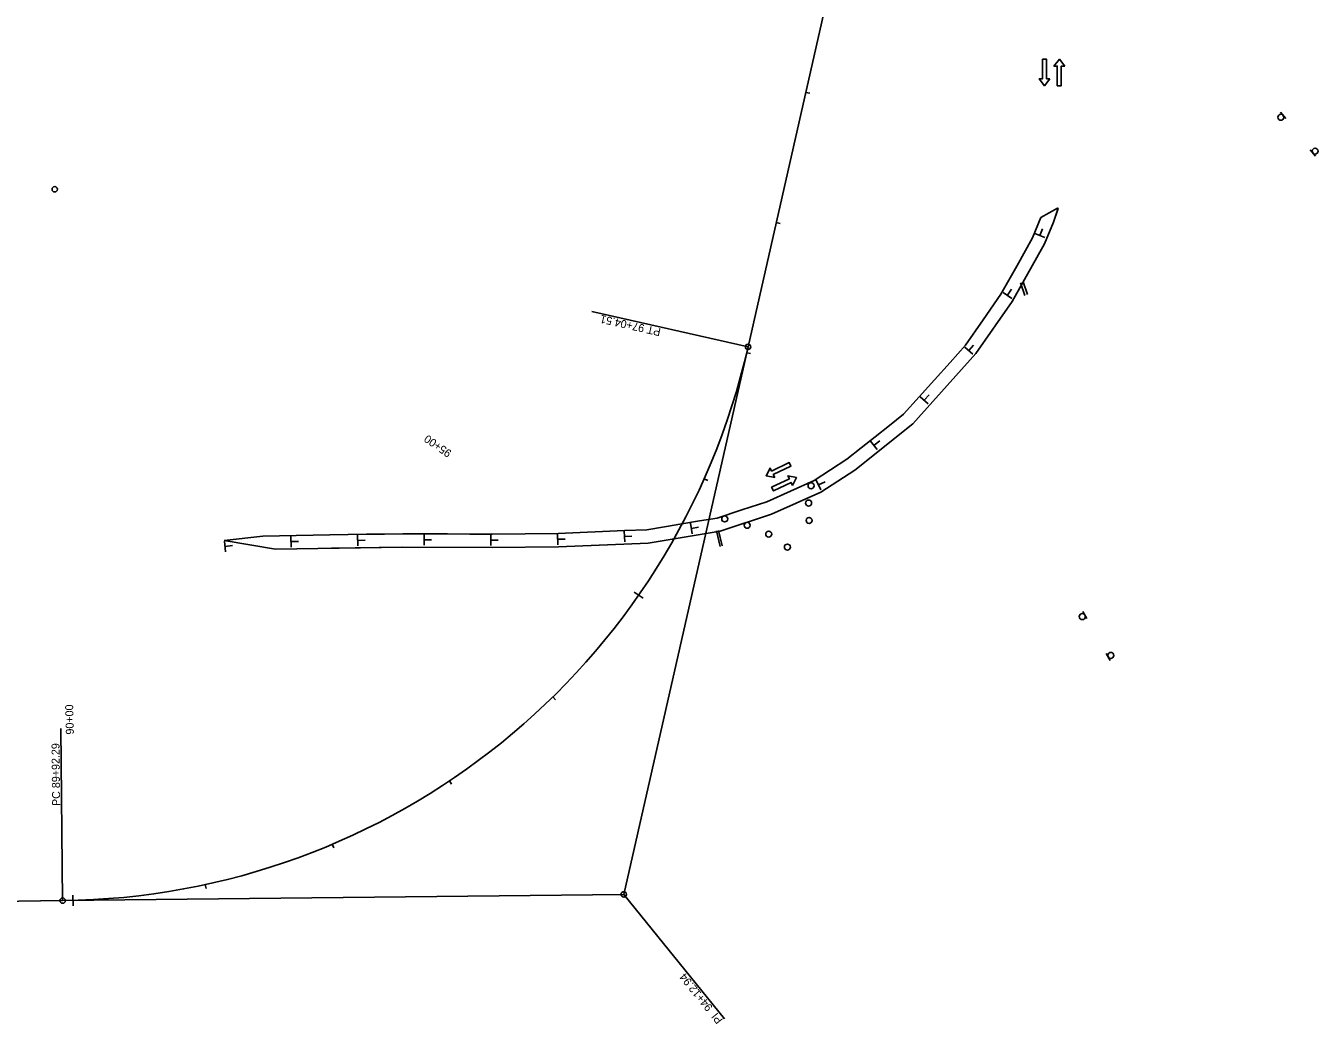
# Model space of a CAD drawing. Extents: x 1710760 to 1712674, y 548603 to 551099.
# Drawn here: x 1711705 to 1712674, y 549120 to 549868 of the extents above; entities that cross this region are included whole.
import ezdxf

# ---------------------------------------------------------------- set-up
doc = ezdxf.new("R2010")
doc.units = 0
for name, color, linetype in [('R_Horz Alg', 7, 'Continuous'), ('R_Horz Alg Annot', 7, 'Continuous'), ('R_MOT', 7, 'Continuous')]:
    doc.layers.add(name, color=color, linetype=linetype)

msp = doc.modelspace()

# ---------------------------------------------------------------- linework, layer by layer
at = {"layer": 'R_Horz Alg'}
for p, q in [((1712246.77, 549627.28), (1712450.81, 550525.82)), ((1711391.77, 549208.53), (1711733, 549212.35))]:
    msp.add_line(p, q, dxfattribs=at)
msp.add_arc((1711727.02, 549745.3), 532.98, 270.64281, 347.20664, dxfattribs=at)
at = {"layer": 'R_Horz Alg Annot'}
for p, q in [((1712153.63, 549217.07), (1712246.77, 549627.28)), ((1711733, 549212.35), (1712153.63, 549217.07))]:
    msp.add_line(p, q, dxfattribs=at)
for points in [[(1712292.99, 549817.25), (1712290.06, 549817.92)], [(1712270.84, 549719.73), (1712267.92, 549720.4)], [(1712246.77, 549627.28), (1712129.75, 549653.86)], [(1712248.68, 549622.2), (1712245.76, 549622.89)], [(1712216.56, 549527.06), (1712213.82, 549528.28)], [(1712161.51, 549443.57), (1712168.08, 549439.01)], [(1712102.51, 549362.83), (1712100.41, 549364.97)], [(1711733, 549212.35), (1711731.55, 549341.4)], [(1712024.58, 549299.5), (1712022.91, 549302)], [(1711936.2, 549251.82), (1711935.03, 549254.59)], [(1711840.48, 549221.47), (1711839.85, 549224.4)], [(1711740.6, 549216.49), (1711740.81, 549208.5)], [(1712153.63, 549217.07), (1712229.02, 549123.72)]]:
    msp.add_lwpolyline(points, dxfattribs=at)
for centre in [(1711727.02, 549745.3), (1712246.77, 549627.28), (1711733, 549212.35), (1712153.63, 549217.07)]:
    msp.add_circle(centre, 2, dxfattribs=at)
at = {"layer": 'R_MOT'}
for p, q in [((1712646, 549802.98), (1712649.82, 549798.35)), ((1712672.08, 549770.13), (1712668.25, 549774.76)), ((1712465.59, 549710.68), (1712467.62, 549715.75)), ((1712461.85, 549712.06), (1712469.28, 549709.08)), ((1712437.93, 549668.04), (1712444.52, 549663.51)), ((1712441.27, 549665.88), (1712444.37, 549670.38)), ((1712451.09, 549675.27), (1712454.25, 549665.78)), ((1712452.99, 549675.9), (1712456.15, 549666.41)), ((1712412.27, 549624.48), (1712415.9, 549628.56)), ((1712409.22, 549627.04), (1712415.2, 549621.72)), ((1712375.81, 549589.84), (1712381.79, 549584.53)), ((1712378.86, 549587.29), (1712382.49, 549591.36)), ((1712338.64, 549556.52), (1712343.64, 549550.27)), ((1712341.22, 549553.48), (1712345.49, 549556.9)), ((1712297.92, 549527.35), (1712301.23, 549520.07)), ((1712299.67, 549523.78), (1712304.64, 549526.04)), ((1712203.59, 549495.16), (1712204.93, 549487.27)), ((1711904.04, 549485.28), (1711904.24, 549477.28)), ((1711954.02, 549486.21), (1711954.19, 549478.21)), ((1712004.01, 549486.65), (1712004, 549478.65)), ((1712004.12, 549482.67), (1712009.58, 549482.67)), ((1712054.01, 549486.38), (1712054, 549478.38)), ((1712104.01, 549487.04), (1712104.16, 549479.04)), ((1712104.2, 549483.06), (1712109.66, 549483.16)), ((1712153.99, 549489.05), (1712154.35, 549481.06)), ((1712154.28, 549485.08), (1712159.74, 549485.33)), ((1712204.37, 549491.25), (1712209.75, 549492.17)), ((1712223.25, 549489.42), (1712225.93, 549477.72)), ((1712224.71, 549489.75), (1712227.39, 549478.06)), ((1711854.26, 549481.66), (1711855.18, 549473.71)), ((1711854.84, 549477.72), (1711860.26, 549478.35)), ((1711904.25, 549481.31), (1711909.71, 549481.44)), ((1711954.22, 549482.23), (1711959.68, 549482.34)), ((1712054.12, 549482.4), (1712059.58, 549482.4)), ((1712497.72, 549428.91), (1712500.76, 549423.74)), ((1712518.29, 549392.37), (1712515.25, 549397.54))]:
    msp.add_line(p, q, dxfattribs=at)
for points in [[(1712473.07, 549828.06), (1712469.06, 549822.88), (1712465.07, 549828.08), (1712467.57, 549828.07), (1712467.6, 549842.79), (1712470.6, 549842.78), (1712470.57, 549828.07)], [(1712484.13, 549837.56), (1712480.14, 549842.76), (1712476.13, 549837.58), (1712478.63, 549837.57), (1712478.6, 549822.86), (1712481.6, 549822.85), (1712481.63, 549837.56)], [(1712266.76, 549529.27), (1712260.35, 549530.63), (1712263.3, 549536.48), (1712264.38, 549534.23), (1712277.64, 549540.6), (1712278.94, 549537.9), (1712265.68, 549531.53)], [(1712280.12, 549523.45), (1712283.07, 549529.3), (1712276.66, 549530.66), (1712277.74, 549528.41), (1712264.48, 549522.03), (1712265.78, 549519.33), (1712279.04, 549525.7)]]:
    msp.add_lwpolyline(points, close=True, dxfattribs=at)
for points in [[(1712479.31, 549731.25), (1712475.64, 549720.74), (1712469.03, 549704.48), (1712444.83, 549661.33), (1712417.63, 549622.18), (1712370.31, 549569.49), (1712326.78, 549534.99), (1712301.26, 549518.44), (1712264.39, 549501.86), (1712225.96, 549489.24), (1712171.87, 549480.27), (1712104.69, 549477.54), (1712055.07, 549476.88), (1711988.09, 549477.23), (1711892.63, 549475.74), (1711854.19, 549482.15)], [(1712479.18, 549730.88), (1712475.64, 549720.74), (1712469.03, 549704.48), (1712444.83, 549661.33), (1712417.63, 549622.18), (1712370.31, 549569.49), (1712326.78, 549534.99), (1712301.26, 549518.44), (1712264.39, 549501.86), (1712225.96, 549489.24), (1712171.87, 549480.27), (1712104.69, 549477.54), (1712055.07, 549476.88), (1711988.09, 549477.23), (1711892.67, 549475.74), (1711854.19, 549482.15)], [(1712479.31, 549731.25), (1712475.64, 549720.74), (1712469.03, 549704.48), (1712444.83, 549661.33), (1712417.63, 549622.18), (1712370.31, 549569.49), (1712326.78, 549534.99), (1712301.26, 549518.44), (1712264.39, 549501.86), (1712225.96, 549489.24), (1712171.87, 549480.27), (1712104.69, 549477.54), (1712055.07, 549476.88), (1711988.09, 549477.23), (1711934.59, 549476.4)], [(1712466.23, 549724.16), (1712478.67, 549731.15), (1712479.18, 549730.88)], [(1711854.19, 549482.15), (1711882.94, 549485.35), (1711895.54, 549485.61), (1711908.15, 549485.86), (1711920.76, 549486.12), (1711933.37, 549486.38), (1711947.04, 549486.59), (1711960.71, 549486.81), (1711974.37, 549487.02), (1711988.04, 549487.23), (1712004.79, 549487.15), (1712021.54, 549487.06), (1712038.29, 549486.97), (1712055.03, 549486.88), (1712079.73, 549487.21), (1712104.42, 549487.54), (1712121.03, 549488.21), (1712137.63, 549488.89), (1712154.24, 549489.56), (1712170.84, 549490.23), (1712184.03, 549492.42), (1712197.21, 549494.6), (1712210.39, 549496.79), (1712223.57, 549498.98), (1712242.17, 549505.09), (1712260.77, 549511.2), (1712278.61, 549519.22), (1712296.46, 549527.24), (1712308.7, 549535.18), (1712320.94, 549543.12), (1712331.56, 549551.54), (1712342.19, 549559.96), (1712352.81, 549568.38), (1712363.43, 549576.8), (1712375.02, 549589.7), (1712386.6, 549602.6), (1712398.19, 549615.5), (1712409.78, 549628.4), (1712423.06, 549647.52), (1712436.35, 549666.64), (1712448.17, 549687.73), (1712460, 549708.82), (1712466.23, 549724.16)]]:
    msp.add_lwpolyline(points, dxfattribs=at)
for centre in [(1712646.18, 549799.23), (1712671.9, 549773.88), (1712294.04, 549523.21), (1712292.2, 549510.26), (1712229.26, 549498.36), (1712246.1, 549493.6), (1712292.56, 549497.19), (1712262.27, 549486.93), (1712276.24, 549477.23), (1712497.3, 549425.18), (1712518.71, 549396.1)]:
    msp.add_circle(centre, 2.25, dxfattribs=at)

# ---------------------------------------------------------------- texts
at = {"layer": 'R_Horz Alg Annot'}
for s, rotation, p in [('PT 97+04.51', 167.20664, (1712181.78, 549641.02)), ('95+00', 145.22143, (1712025.13, 549548.9)), ('90+00', 91.47143, (1711741.42, 549336.87)), ('PC 89+92.29', 90.64281, (1711731.15, 549283.3)), ('PI  94+12.94', 128.92472, (1712228.24, 549123.09))]:
    msp.add_text(s, height=6, rotation=rotation, dxfattribs=at).set_placement(p)

doc.saveas('drawing.dxf')
